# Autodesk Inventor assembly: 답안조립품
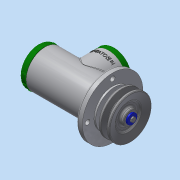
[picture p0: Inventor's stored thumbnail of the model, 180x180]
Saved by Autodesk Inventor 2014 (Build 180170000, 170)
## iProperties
Created: 2016-08
Part Number: 답안조립품
Document SubType Name: Assembly
Designer: 402-003
Author: 402-003
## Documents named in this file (25)
- C:\Users\402-003\Desktop\460807V1027\답안조립품.iam
- C:\Users\402-003\Desktop\460807V1027\본체.ipt
- C:\Users\402-003\Desktop\460807V1027\460807V1027\V-벨트풀리.ipt
- C:\Users\402-003\Desktop\460807V1027\460807V1027\너트 M10.ipt
- C:\Users\402-003\Desktop\460807V1027\460807V1027\링크.ipt
- C:\Users\402-003\Desktop\460807V1027\460807V1027\멈춤링 15 x 1.ipt
- C:\Users\402-003\Desktop\460807V1027\460807V1027\멈춤링 35x1.6.ipt
- C:\Users\402-003\Desktop\460807V1027\460807V1027\베어링 15 x 35 x 11.ipt
- C:\Users\402-003\Desktop\460807V1027\460807V1027\볼트 M4 x 10.ipt
- C:\Users\402-003\Desktop\460807V1027\460807V1027\볼트 M4 x 12.ipt
- C:\Users\402-003\Desktop\460807V1027\460807V1027\부시1.ipt
- C:\Users\402-003\Desktop\460807V1027\460807V1027\부시2.ipt
- C:\Users\402-003\Desktop\460807V1027\460807V1027\분할핀 1.6 x 12.ipt
- C:\Users\402-003\Desktop\460807V1027\460807V1027\사이드 커버.ipt
- 사이드 커버.ipt
- C:\Users\402-003\Desktop\460807V1027\460807V1027\슬라이더.ipt
- C:\Users\402-003\Desktop\460807V1027\460807V1027\오일 실 15 25 7.ipt
- C:\Users\402-003\Desktop\460807V1027\460807V1027\와셔 4x16.ipt
- C:\Users\402-003\Desktop\460807V1027\460807V1027\와셔 10x21.ipt
- C:\Users\402-003\Desktop\460807V1027\460807V1027\클래스터 핀 6 x 24.ipt
- C:\Users\402-003\Desktop\460807V1027\460807V1027\키 4 x 4 x 18.ipt
- C:\Users\402-003\Desktop\460807V1027\460807V1027\탑 부시.ipt
- C:\Users\402-003\Desktop\460807V1027\460807V1027\탑 커버.ipt
- 탑 커버.ipt
- C:\Users\402-003\Desktop\460807V1027\460807V1027\편심축.ipt
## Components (6 placed, 3 different names)
1. V-벨트풀리:1
2. ISO 4017 M4 x 10:1
3. ISO 4762 M4 x 12:1
4. ISO 4762 M4 x 12:2
5. ISO 4762 M4 x 12:3
6. ISO 4762 M4 x 12:4
